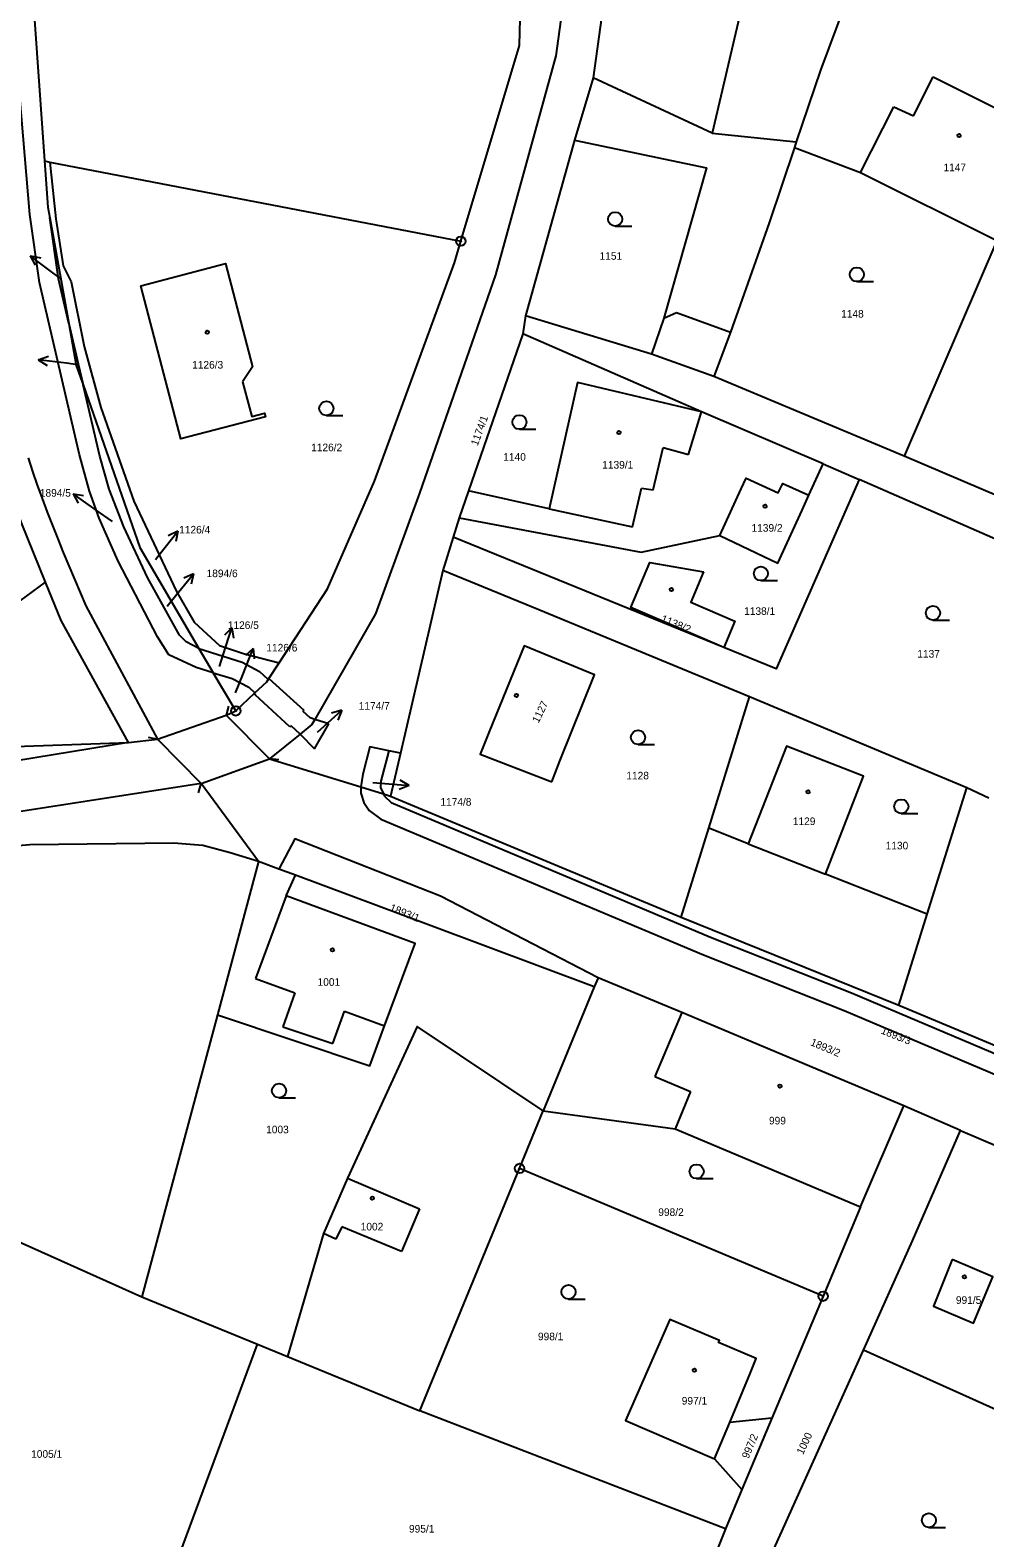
# Model space of a CAD drawing. Extents: x -587171 to -555306, y -1167727 to -1074732.
# Drawn here: x -560055 to -559954, y -1077384.9 to -1077225.4 of the extents above; entities that cross this region are included whole.
import ezdxf

# ---------------------------------------------------------------- set-up
doc = ezdxf.new("R2010")
doc.units = 0
for name, color, linetype in [('Hranice parcel', 7, 'Continuous'), ('Parcelní čísla', 7, 'Continuous'), ('Pop  PČ popisy', 7, 'Continuous'), ('Vnitřní kresba', 7, 'Continuous'), ('Značky bodu BP', 7, 'Continuous'), ('Značky budov', 7, 'Continuous'), ('Značky kultur', 7, 'Continuous')]:
    doc.layers.add(name, color=color, linetype=linetype)

msp = doc.modelspace()

# ---------------------------------------------------------------- linework, layer by layer
at = {"layer": 'Hranice parcel'}
for p, q in [((-560054.68, -1077221.83), (-560053.43, -1077239.27)), ((-559995.39, -1077230.48), (-559997.38, -1077237.06)), ((-559997.38, -1077237.06), (-560002.57, -1077255.66)), ((-560053.43, -1077239.27), (-560052.86, -1077239.38)), ((-560052.86, -1077239.38), (-560009.4, -1077247.76)), ((-560052.86, -1077239.38), (-560052.24, -1077245.4)), ((-560052.88, -1077245.28), (-560050.87, -1077256.47)), ((-560051.97, -1077251.73), (-560052.88, -1077245.28)), ((-559952.71, -1077247.67), (-559962.52, -1077270.5)), ((-560050.87, -1077256.47), (-560051.97, -1077251.73)), ((-560050.87, -1077256.47), (-560049.88, -1077260.71)), ((-560002.57, -1077255.66), (-560002.85, -1077257.55)), ((-559989.22, -1077259.69), (-560002.57, -1077255.66)), ((-560002.85, -1077257.55), (-560008.59, -1077274.16)), ((-559983.95, -1077265.8), (-560002.85, -1077257.55)), ((-559982.64, -1077262.05), (-559989.22, -1077259.69)), ((-560049.88, -1077260.71), (-560049.36, -1077262.96)), ((-560047.59, -1077270.51), (-560049.36, -1077262.96)), ((-559962.52, -1077270.5), (-559982.64, -1077262.05)), ((-559971.06, -1077271.31), (-559983.95, -1077265.8)), ((-559943.24, -1077278.73), (-559962.52, -1077270.5)), ((-559972.57, -1077274.63), (-559971.06, -1077271.31)), ((-559971.06, -1077271.31), (-559967.26, -1077272.96)), ((-560008.59, -1077274.16), (-560009.57, -1077277)), ((-559942.85, -1077283.65), (-559967.26, -1077272.96)), ((-560009.57, -1077277), (-560010.22, -1077279.07)), ((-560010.22, -1077279.07), (-560011.29, -1077282.6)), ((-560037.1, -1077290.82), (-560035.58, -1077293.41)), ((-560032.27, -1077291.41), (-560028.61, -1077292.34)), ((-560029.7, -1077294), (-560028.61, -1077292.34)), ((-560033.2, -1077297.44), (-560035.58, -1077293.41)), ((-560031.82, -1077294.93), (-560031.19, -1077295.54)), ((-560029.84, -1077294.05), (-560029.7, -1077294)), ((-560033.2, -1077297.44), (-560031.19, -1077295.54)), ((-559983.17, -1077309.84), (-559978.88, -1077295.93)), ((-559955.87, -1077305.57), (-559978.88, -1077295.93)), ((-560041.5, -1077300.43), (-560034.22, -1077297.9)), ((-560034.22, -1077297.9), (-560033.2, -1077297.44)), ((-560024.86, -1077301.44), (-560023.35, -1077298.79)), ((-560023.35, -1077298.79), (-560024.84, -1077298.33)), ((-560064.86, -1077301.48), (-560044.56, -1077300.76)), ((-560044.56, -1077300.76), (-560064.32, -1077304.02)), ((-560044.56, -1077300.76), (-560041.5, -1077300.43)), ((-560026.41, -1077299.9), (-560029.63, -1077302.5)), ((-560026.41, -1077299.9), (-560024.86, -1077301.44)), ((-560036.87, -1077305.12), (-560029.63, -1077302.5)), ((-560029.63, -1077302.5), (-560019.98, -1077305.47)), ((-560015.77, -1077301.91), (-560016.82, -1077306.44)), ((-560019.77, -1077304.12), (-560019.98, -1077305.47)), ((-560030.81, -1077313.36), (-560036.87, -1077305.12)), ((-560019.98, -1077305.47), (-560019.97, -1077306.15)), ((-559960.06, -1077318.93), (-559955.87, -1077305.57)), ((-559953.55, -1077306.68), (-559955.87, -1077305.57)), ((-560016.82, -1077306.44), (-559986.08, -1077319.26)), ((-559986.08, -1077319.26), (-559983.17, -1077309.84)), ((-560030.81, -1077313.36), (-560035.15, -1077329.59)), ((-560028.64, -1077314.17), (-560030.81, -1077313.36)), ((-560026.89, -1077314.82), (-560028.64, -1077314.17)), ((-559986.08, -1077319.26), (-559963.08, -1077328.55)), ((-559963.08, -1077328.55), (-559960.06, -1077318.93)), ((-559995.29, -1077326.62), (-560000.68, -1077339.72)), ((-559994.88, -1077325.68), (-559995.29, -1077326.62)), ((-560035.15, -1077329.59), (-560043.13, -1077359.42)), ((-559963.08, -1077328.55), (-559929.98, -1077342.38)), ((-559967.11, -1077349.89), (-559962.53, -1077339.19)), ((-559956.53, -1077341.81), (-559962.53, -1077339.19)), ((-560003.19, -1077345.82), (-560000.68, -1077339.72)), ((-559956.53, -1077341.81), (-559930.55, -1077352.91)), ((-560013.73, -1077371.45), (-560003.19, -1077345.82)), ((-559971.08, -1077359.35), (-560003.19, -1077345.82)), ((-559967.11, -1077349.89), (-559971.08, -1077359.35)), ((-560062.31, -1077350.83), (-560043.13, -1077359.42)), ((-560043.13, -1077359.42), (-560030.92, -1077364.43)), ((-559971.08, -1077359.35), (-559976.49, -1077372.24)), ((-560030.92, -1077364.43), (-560027.75, -1077365.72)), ((-559978.26, -1077390.49), (-559966.82, -1077365.06)), ((-559949.05, -1077373.02), (-559966.82, -1077365.06)), ((-560027.75, -1077365.72), (-560013.73, -1077371.45)), ((-559981.41, -1077383.96), (-560013.73, -1077371.45)), ((-559982.56, -1077376.53), (-559980.95, -1077372.68)), ((-559976.49, -1077372.24), (-559980.95, -1077372.68)), ((-559976.49, -1077372.24), (-559979.66, -1077379.8)), ((-559982.56, -1077376.53), (-559979.66, -1077379.8)), ((-559979.66, -1077379.8), (-559981.41, -1077383.96))]:
    msp.add_line(p, q, dxfattribs=at)
for points in [[(-560004.91, -1077196.43), (-560000.94, -1077209.74), (-559999.02, -1077218.69), (-559998.7, -1077223.52), (-559999.36, -1077228.15), (-560005.72, -1077251.33), (-560013.76, -1077274.39)], [(-559996.81, -1077201.54), (-559994.46, -1077218.47), (-559994.51, -1077224.08), (-559995.39, -1077230.48)], [(-559965.84, -1077214.88), (-559978.13, -1077215.06), (-559975.89, -1077203.26), (-559984.4, -1077201.67), (-559987.96, -1077220.4), (-559979.41, -1077221.85), (-559982.81, -1077236.32), (-559995.39, -1077230.48)], [(-560009.4, -1077247.76), (-560003.19, -1077227.07), (-560003.02, -1077219.85), (-560005.01, -1077210.73), (-560007.64, -1077202.6)], [(-559965.84, -1077214.88), (-559971.37, -1077229.65), (-559973.91, -1077237.24), (-559974.12, -1077237.85)], [(-560035.58, -1077293.41), (-560037.41, -1077292.85), (-560040.27, -1077291.52), (-560041.49, -1077289.6), (-560045.64, -1077281.6), (-560047.66, -1077277.04), (-560048.67, -1077274.19), (-560049.75, -1077270.34), (-560053.97, -1077252.12), (-560054.98, -1077244.94), (-560056.91, -1077222), (-560054.68, -1077221.83)], [(-559997.38, -1077237.06), (-559983.41, -1077240.01), (-559987.92, -1077255.9), (-559989.22, -1077259.69)], [(-559974.12, -1077237.85), (-559976.78, -1077245.81), (-559980.88, -1077257.37), (-559982.64, -1077262.05)], [(-559974.12, -1077237.85), (-559967.13, -1077240.5), (-559952.71, -1077247.67)], [(-560053.43, -1077239.27), (-560053.08, -1077244.17), (-560052.88, -1077245.28)], [(-560052.24, -1077245.4), (-560051.46, -1077250.37), (-560050.6, -1077252.05), (-560049.23, -1077258.9), (-560047.48, -1077265.33), (-560043.97, -1077275.26), (-560039.49, -1077284.79), (-560037.62, -1077288.04), (-560034.91, -1077290.53), (-560032.27, -1077291.41)], [(-560018.52, -1077273.13), (-560010.08, -1077250.04), (-560009.4, -1077247.76)], [(-560032.51, -1077262.63), (-560031.51, -1077266.28), (-560030.15, -1077265.95), (-560030.06, -1077266.33), (-560039.03, -1077268.67), (-560043.24, -1077252.47), (-560034.28, -1077250.12), (-560031.43, -1077261.04), (-560032.51, -1077262.63)], [(-560050.87, -1077256.47), (-560050.07, -1077260.9), (-560049.36, -1077262.96)], [(-560049.36, -1077262.96), (-560043.37, -1077280.17), (-560037.1, -1077290.82)], [(-559983.95, -1077265.8), (-559997.04, -1077262.7), (-560000.06, -1077276.05), (-560008.59, -1077274.16)], [(-560037.1, -1077290.82), (-560038.44, -1077290.13), (-560039.17, -1077289.44), (-560042.54, -1077283.32), (-560045.03, -1077277.95), (-560046.58, -1077273.97), (-560047.59, -1077270.51)], [(-560057.98, -1077271.54), (-560065.49, -1077272.57), (-560069.35, -1077275.45), (-560067.04, -1077278.6), (-560072.54, -1077282.66), (-560069.64, -1077286.59), (-560071.09, -1077287.6), (-560070.73, -1077288.09), (-560070.5, -1077287.92), (-560066.39, -1077293.38), (-560059.41, -1077288.26), (-560053.34, -1077283.81)], [(-560053.34, -1077283.81), (-560055.88, -1077277.54), (-560057.98, -1077271.54)], [(-560028.61, -1077292.34), (-560023.49, -1077284.53), (-560018.52, -1077273.13)], [(-559967.26, -1077272.96), (-559976.03, -1077293), (-560010.22, -1077279.07)], [(-559981.99, -1077278.87), (-559979.73, -1077273.96), (-559979.2, -1077272.81), (-559975.84, -1077274.36), (-559975.35, -1077273.37), (-559972.57, -1077274.63)], [(-560013.76, -1077274.39), (-560018.44, -1077287.18), (-560024.84, -1077298.33)], [(-559981.99, -1077278.87), (-559975.85, -1077281.82), (-559973.29, -1077276.2), (-559972.57, -1077274.63)], [(-560009.57, -1077277), (-559990.34, -1077280.65), (-559981.99, -1077278.87)], [(-559983.74, -1077282.73), (-559985.07, -1077285.94), (-559980.42, -1077287.95), (-559981.57, -1077290.72), (-559991.42, -1077286.5), (-559989.39, -1077281.75), (-559983.74, -1077282.73)], [(-560011.29, -1077282.6), (-560015.1, -1077299), (-560015.77, -1077301.91)], [(-559978.88, -1077295.93), (-560001.16, -1077286.76), (-560011.29, -1077282.6)], [(-560044.56, -1077300.76), (-560051.68, -1077287.88), (-560053.34, -1077283.81)], [(-560037.1, -1077290.82), (-560032.52, -1077292.28), (-560030.7, -1077293.28), (-560029.84, -1077294.05)], [(-559999.77, -1077304.94), (-559998.9, -1077302.66), (-559995.25, -1077293.62), (-560002.7, -1077290.57), (-560006.42, -1077299.73), (-560007.34, -1077302.01), (-559999.77, -1077304.94)], [(-560035.58, -1077293.41), (-560033.58, -1077294.01), (-560031.82, -1077294.93)], [(-560031.19, -1077295.54), (-560029.93, -1077294.35), (-560029.7, -1077294)], [(-560024.84, -1077298.33), (-560025.15, -1077298.88), (-560026.41, -1077299.9)], [(-560015.77, -1077301.91), (-560017.02, -1077301.65), (-560019.02, -1077301.24), (-560019.77, -1077304.12)], [(-559960.06, -1077318.93), (-559970.81, -1077314.7), (-559966.79, -1077304.34), (-559974.94, -1077301.15), (-559979, -1077311.48), (-559983.17, -1077309.84)], [(-560036.87, -1077305.12), (-560057.31, -1077308.27), (-560078.28, -1077311.55), (-560114.62, -1077325.3), (-560129.62, -1077334.71)], [(-560019.98, -1077305.47), (-560017.57, -1077306.21), (-560016.82, -1077306.44)], [(-560019.97, -1077306.15), (-560019.65, -1077307.12), (-560019.09, -1077307.96), (-560017.85, -1077308.9), (-559983.72, -1077323.25), (-559968.84, -1077329.13), (-559950.38, -1077336.96), (-559922.87, -1077348.95), (-559908.29, -1077354.69), (-559906.95, -1077355.04)], [(-560030.81, -1077313.36), (-560033.78, -1077312.44), (-560036.69, -1077311.68), (-560039.79, -1077311.41), (-560054.98, -1077311.59), (-560063.88, -1077312.39), (-560075.71, -1077315.12), (-560089.9, -1077319.46), (-560101.1, -1077323.43), (-560106.22, -1077325.48)], [(-559994.88, -1077325.68), (-560011.55, -1077317.03), (-560026.95, -1077310.97), (-560028.64, -1077314.17)], [(-560035.15, -1077329.59), (-560019.01, -1077334.99), (-560017.48, -1077330.74), (-560014.22, -1077322.02), (-560027.88, -1077316.99), (-560026.89, -1077314.82)], [(-559995.29, -1077326.62), (-560012.52, -1077320.18), (-560026.89, -1077314.82)], [(-559962.53, -1077339.19), (-559986.03, -1077329.34), (-559994.88, -1077325.68)], [(-560000.68, -1077339.72), (-560014.03, -1077330.81), (-560021.39, -1077346.86), (-560023.92, -1077352.7), (-560027.75, -1077365.72)], [(-560000.68, -1077339.72), (-559986.71, -1077341.63), (-559967.11, -1077349.89)], [(-559966.82, -1077365.06), (-559961.61, -1077353.47), (-559956.53, -1077341.81)], [(-559957.42, -1077355.46), (-559959.4, -1077360.41), (-559955.16, -1077362.19), (-559953.13, -1077357.3), (-559957.42, -1077355.46)], [(-559980.95, -1077372.68), (-559978.78, -1077367.5), (-559978.15, -1077365.93), (-559982.13, -1077364.22), (-559982.05, -1077364.03), (-559987.3, -1077361.8), (-559991.97, -1077372.48), (-559982.56, -1077376.53)], [(-560031.56, -1077394.23), (-560040.52, -1077390.39), (-560030.92, -1077364.43)], [(-559981.41, -1077383.96), (-559985.09, -1077393.19), (-559990.04, -1077404.64)]]:
    msp.add_lwpolyline(points, dxfattribs=at)
at = {"layer": 'Pop  PČ popisy'}
for p, q in [((-560052.54, -1077251.1), (-560054.94, -1077249.29)), ((-560054.94, -1077249.29), (-560053.84, -1077249.5)), ((-560054.94, -1077249.29), (-560054.44, -1077250.3)), ((-560051.77, -1077251.68), (-560052.54, -1077251.1)), ((-560054.09, -1077260.3), (-560053.03, -1077259.93)), ((-560051.11, -1077260.67), (-560054.09, -1077260.3)), ((-560054.09, -1077260.3), (-560053.16, -1077260.92)), ((-560049.96, -1077260.82), (-560051.11, -1077260.67)), ((-560047.96, -1077276.21), (-560050.42, -1077274.49)), ((-560050.42, -1077274.49), (-560049.31, -1077274.65)), ((-560050.42, -1077274.49), (-560049.89, -1077275.47)), ((-560046.26, -1077277.41), (-560047.96, -1077276.21)), ((-560041.19, -1077280.79), (-560039.34, -1077278.43)), ((-560039.34, -1077278.43), (-560040.35, -1077278.91)), ((-560039.34, -1077278.43), (-560039.56, -1077279.52)), ((-560041.69, -1077281.42), (-560041.19, -1077280.79)), ((-560039.57, -1077285.27), (-560037.68, -1077282.94)), ((-560037.68, -1077282.94), (-560038.7, -1077283.4)), ((-560037.68, -1077282.94), (-560037.92, -1077284.03)), ((-560040.47, -1077286.37), (-560039.57, -1077285.27)), ((-560034.54, -1077291.5), (-560033.61, -1077288.65)), ((-560033.61, -1077288.65), (-560034.4, -1077289.44)), ((-560033.61, -1077288.65), (-560033.45, -1077289.75)), ((-560034.94, -1077292.73), (-560034.54, -1077291.5)), ((-560032.47, -1077293.61), (-560031.35, -1077290.83)), ((-560031.35, -1077290.83), (-560032.19, -1077291.57)), ((-560031.35, -1077290.83), (-560031.26, -1077291.94)), ((-560033.24, -1077295.52), (-560032.47, -1077293.61)), ((-560024.22, -1077299.37), (-560021.99, -1077297.36)), ((-560021.99, -1077297.36), (-560023.07, -1077297.66)), ((-560021.99, -1077297.36), (-560022.4, -1077298.4)), ((-560024.56, -1077299.67), (-560024.22, -1077299.37)), ((-560018.69, -1077305), (-560017.87, -1077305.07)), ((-560017.87, -1077305.07), (-560014.88, -1077305.33)), ((-560014.88, -1077305.33), (-560015.92, -1077305.74)), ((-560014.88, -1077305.33), (-560015.83, -1077304.75))]:
    msp.add_line(p, q, dxfattribs=at)
at = {"layer": 'Vnitřní kresba'}
for p, q in [((-559961.51, -1077234.5), (-559959.44, -1077230.38)), ((-559959.44, -1077230.38), (-559947.23, -1077236.5)), ((-559967.13, -1077240.5), (-559963.6, -1077233.54)), ((-559963.6, -1077233.54), (-559961.51, -1077234.5)), ((-559982.81, -1077236.32), (-559973.91, -1077237.24)), ((-559987.92, -1077255.9), (-559986.57, -1077255.3)), ((-559986.57, -1077255.3), (-559980.88, -1077257.37)), ((-559985.32, -1077270.3), (-559983.95, -1077265.8)), ((-559989.07, -1077274.04), (-559988, -1077269.56)), ((-559988, -1077269.56), (-559985.32, -1077270.3)), ((-559991.24, -1077277.98), (-559990.27, -1077273.86)), ((-559990.27, -1077273.86), (-559989.07, -1077274.04)), ((-560000.06, -1077276.05), (-559991.24, -1077277.98)), ((-560049.08, -1077286.32), (-560041.5, -1077300.43)), ((-560029.7, -1077294), (-560026, -1077297.36)), ((-560031.11, -1077295.61), (-560031.19, -1077295.54)), ((-560031.17, -1077295.73), (-560031.11, -1077295.61)), ((-560027.48, -1077299.12), (-560031.17, -1077295.73)), ((-560033.98, -1077296.93), (-560034.22, -1077297.9)), ((-560029.63, -1077302.5), (-560034.22, -1077297.9)), ((-560026.07, -1077297.5), (-560026, -1077297.36)), ((-560025.33, -1077298.18), (-560026.07, -1077297.5)), ((-560027.35, -1077299.01), (-560027.48, -1077299.12)), ((-560026.41, -1077299.9), (-560027.35, -1077299.01)), ((-560024.84, -1077298.33), (-560025.33, -1077298.18)), ((-560042.47, -1077300.2), (-560041.5, -1077300.43)), ((-560041.5, -1077300.43), (-560036.87, -1077305.12)), ((-560028.64, -1077302.6), (-560029.63, -1077302.5)), ((-560017.02, -1077301.65), (-560017.86, -1077304.87)), ((-560037.13, -1077306.09), (-560036.87, -1077305.12)), ((-560017.86, -1077304.87), (-560017.89, -1077305.54)), ((-560017.89, -1077305.54), (-560017.57, -1077306.21)), ((-560017.57, -1077306.21), (-560017.46, -1077306.44)), ((-560017.46, -1077306.44), (-560016.75, -1077307.12)), ((-560016.75, -1077307.12), (-559983, -1077321.36)), ((-559979, -1077311.48), (-559970.81, -1077314.7)), ((-560027.88, -1077316.99), (-560031.1, -1077325.74)), ((-559983, -1077321.36), (-559968.06, -1077327.24)), ((-560031.1, -1077325.74), (-560026.95, -1077327.27)), ((-560026.95, -1077327.27), (-560028.23, -1077330.85)), ((-559968.06, -1077327.24), (-559949.59, -1077335.09)), ((-560022.94, -1077332.61), (-560021.7, -1077329.19)), ((-560021.7, -1077329.19), (-560017.48, -1077330.74)), ((-559986.03, -1077329.34), (-559988.89, -1077336.1)), ((-560028.23, -1077330.85), (-560022.94, -1077332.61)), ((-559988.89, -1077336.1), (-559985.11, -1077337.7)), ((-559985.11, -1077337.7), (-559986.71, -1077341.63)), ((-560021.39, -1077346.86), (-560013.77, -1077350.11)), ((-560013.77, -1077350.11), (-560015.68, -1077354.61)), ((-560021.99, -1077352.01), (-560022.61, -1077353.32)), ((-560015.68, -1077354.61), (-560021.99, -1077352.01)), ((-560022.61, -1077353.32), (-560023.92, -1077352.7))]:
    msp.add_line(p, q, dxfattribs=at)
msp.add_lwpolyline([(-560055.18, -1077270.68), (-560054.7, -1077272.13), (-560054.2, -1077273.56), (-560053.68, -1077274.98), (-560053.14, -1077276.42), (-560052.59, -1077277.83), (-560052.03, -1077279.25), (-560051.45, -1077280.68), (-560050.86, -1077282.08), (-560050.28, -1077283.49), (-560049.68, -1077284.91), (-560049.08, -1077286.32)], dxfattribs=at)
at = {"layer": 'Značky bodu BP'}
for centre, radius in [((-560009.4, -1077247.76), 0.5), ((-560009.4, -1077247.76), 0.0303), ((-560033.2, -1077297.44), 0.5), ((-560033.2, -1077297.44), 0.0303), ((-560003.19, -1077345.82), 0.5), ((-560003.19, -1077345.82), 0.0303), ((-559971.08, -1077359.35), 0.5), ((-559971.08, -1077359.35), 0.0303)]:
    msp.add_circle(centre, radius, dxfattribs=at)
at = {"layer": 'Značky budov'}
for centre in [(-559956.69, -1077236.58), (-560036.22, -1077257.38), (-559992.67, -1077268), (-559977.21, -1077275.79), (-559987.12, -1077284.6), (-560003.51, -1077295.8), (-559972.67, -1077306), (-560022.98, -1077322.72), (-559975.64, -1077337.11), (-560018.76, -1077348.96), (-559956.13, -1077357.3), (-559984.69, -1077367.17)]:
    msp.add_circle(centre, 0.175, dxfattribs=at)
at = {"layer": 'Značky kultur'}
for p, q in [((-559993.07, -1077246.17), (-559991.32, -1077246.17)), ((-559967.51, -1077252.03), (-559965.76, -1077252.03)), ((-560023.62, -1077266.19), (-560021.87, -1077266.19)), ((-560003.2, -1077267.65), (-560001.45, -1077267.65)), ((-559977.66, -1077283.66), (-559975.91, -1077283.66)), ((-559959.46, -1077287.83), (-559957.71, -1077287.83)), ((-559990.65, -1077300.99), (-559988.9, -1077300.99)), ((-559962.81, -1077308.29), (-559961.06, -1077308.29)), ((-560028.63, -1077338.36), (-560026.88, -1077338.36)), ((-559984.46, -1077346.9), (-559982.71, -1077346.9)), ((-559998.01, -1077359.64), (-559996.26, -1077359.64)), ((-559959.89, -1077383.79), (-559958.14, -1077383.79))]:
    msp.add_line(p, q, dxfattribs=at)
for centre in [(-559993.07, -1077245.42), (-559967.51, -1077251.28), (-560023.62, -1077265.44), (-560003.2, -1077266.9), (-559977.66, -1077282.91), (-559959.46, -1077287.08), (-559990.65, -1077300.24), (-559962.81, -1077307.54), (-560028.63, -1077337.61), (-559984.46, -1077346.15), (-559998.01, -1077358.89), (-559959.89, -1077383.04)]:
    msp.add_circle(centre, 0.75, dxfattribs=at)

# ---------------------------------------------------------------- texts
at = {"layer": 'Parcelní čísla'}
for s, p in [('1147', (-559958.35, -1077240.36)), ('1151', (-559994.72, -1077249.72)), ('1148', (-559969.17, -1077255.84)), ('1126/3', (-560037.82, -1077261.23)), ('1126/2', (-560025.23, -1077269.97)), ('1140', (-560004.91, -1077270.97)), ('1139/1', (-559994.44, -1077271.81)), ('1894/5', (-560053.93, -1077274.78)), ('1126/4', (-560039.19, -1077278.67)), ('1139/2', (-559978.65, -1077278.48)), ('1894/6', (-560036.29, -1077283.29)), ('1138/1', (-559979.43, -1077287.28)), ('1126/5', (-560034.05, -1077288.77)), ('1126/6', (-560029.97, -1077291.15)), ('1137', (-559961.11, -1077291.8)), ('1174/7', (-560020.2, -1077297.31)), ('1128', (-559991.89, -1077304.68)), ('1174/8', (-560011.56, -1077307.46)), ('1129', (-559974.28, -1077309.51)), ('1130', (-559964.46, -1077312.08)), ('1001', (-560024.55, -1077326.51)), ('999', (-559976.8, -1077341.17)), ('1003', (-560029.99, -1077342.11)), ('998/2', (-559988.51, -1077350.85)), ('1002', (-560019.99, -1077352.38)), ('991/5', (-559957.03, -1077360.15)), ('998/1', (-560001.24, -1077364)), ('997/1', (-559986.03, -1077370.8)), ('1005/1', (-560054.85, -1077376.43)), ('995/1', (-560014.88, -1077384.34))]:
    msp.add_text(s, height=0.803, dxfattribs=at).set_placement(p)
for s, rotation, p in [('1174/1', 70, (-560007.62, -1077269.46)), ('1138/2', 338, (-559988.3, -1077287.99)), ('1127', 64, (-560001.18, -1077298.78)), ('1893/1', 338, (-560017, -1077318.55)), ('1893/3', 338, (-559965.03, -1077331.53)), ('1893/2', 337, (-559972.49, -1077332.77)), ('997/2', 67, (-559978.98, -1077376.59)), ('1000', 65, (-559973.2, -1077376.16))]:
    msp.add_text(s, height=0.803, rotation=rotation, dxfattribs=at).set_placement(p)

doc.saveas('drawing.dxf')
